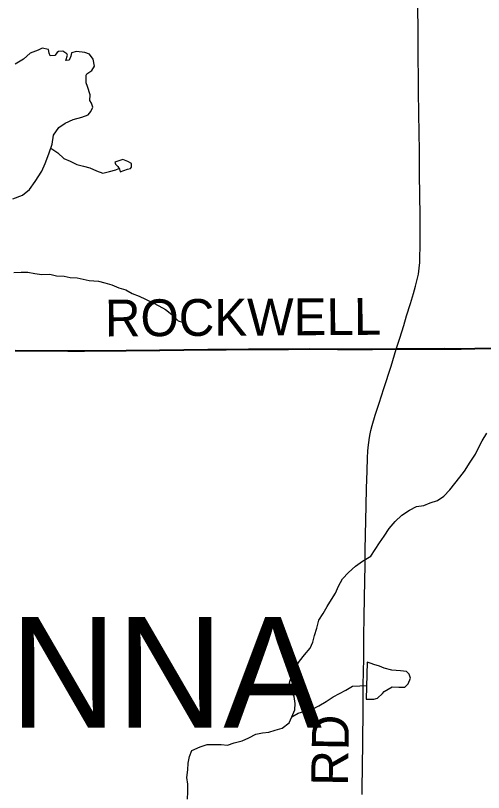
# Model space of a CAD drawing. Extents: x 0 to 34, y 0 to 22.
# Drawn here: x 23.748 to 24.47, y 12.038 to 13.237 of the extents above; entities that cross this region are included whole.
import ezdxf

# ---------------------------------------------------------------- set-up
doc = ezdxf.new("R2010")
doc.units = 0
for name, color, linetype in [('GM_X_Corporation', 7, 'Continuous'), ('GM_X_County_Road', 7, 'Continuous'), ('GM_X_County_Road_Text', 7, 'Continuous'), ('GM_X_Minor_Lake', 7, 'Continuous'), ('GM_X_Minor_River', 7, 'Continuous'), ('GM_X_Township_Text', 7, 'Continuous')]:
    doc.layers.add(name, color=color, linetype=linetype)

msp = doc.modelspace()

# ---------------------------------------------------------------- linework, layer by layer
at = {"layer": 'GM_X_Corporation'}
for points in [[(24.6023, 12.724), (24.4568, 12.7229), (24.4357, 12.7227), (24.4096, 12.7228), (24.3873, 12.7226), (24.3619, 12.7226), (24.3353, 12.7224), (24.299, 12.7222), (24.2598, 12.7221), (24.245, 12.7222), (24.2022, 12.7224), (24.1693, 12.7222), (24.1078, 12.7219), (24.0731, 12.7215), (24.0451, 12.7213), (23.9705, 12.7205), (23.919, 12.7199), (23.8904, 12.7197), (23.8543, 12.7197), (23.8289, 12.7197), (23.7792, 12.7197), (23.7663, 12.7197), (23.7477, 12.7198)], [(23.7477, 12.7198), (23.7663, 12.7197), (23.7792, 12.7197), (23.8289, 12.7197), (23.8543, 12.7197), (23.8904, 12.7197), (23.919, 12.7199), (23.9705, 12.7205), (24.0451, 12.7213), (24.0731, 12.7215), (24.1078, 12.7219), (24.1693, 12.7222), (24.2022, 12.7224), (24.245, 12.7222), (24.2598, 12.7221), (24.299, 12.7222), (24.3353, 12.7224), (24.3619, 12.7226), (24.3873, 12.7226), (24.4096, 12.7228), (24.4357, 12.7227), (24.4568, 12.7229), (24.6023, 12.724)]]:
    msp.add_lwpolyline(points, dxfattribs=at)
at = {"layer": 'GM_X_County_Road'}
for points in [[(24.3355, 12.7219), (24.3411, 12.7391), (24.3472, 12.7587), (24.3517, 12.7733), (24.3577, 12.7927), (24.3622, 12.8079), (24.3654, 12.8191), (24.367, 12.8252), (24.3685, 12.8313), (24.3698, 12.8376), (24.3705, 12.8422), (24.3711, 12.8468), (24.3715, 12.8514), (24.3718, 12.8553), (24.3722, 12.8685), (24.3724, 12.8757), (24.3724, 12.8845), (24.3724, 12.8999), (24.3723, 12.9281), (24.3715, 12.9914), (24.3713, 13.0297), (24.371, 13.0537), (24.3706, 13.0876), (24.3702, 13.1174), (24.3701, 13.1281), (24.3699, 13.1407), (24.3697, 13.1714), (24.3694, 13.2024), (24.3689, 13.2618)], [(24.3355, 12.7219), (24.3621, 12.722), (24.3875, 12.722), (24.4098, 12.7222), (24.4359, 12.7222), (24.457, 12.7223), (24.6025, 12.7234), (24.654, 12.7236), (24.6795, 12.7237), (24.8466, 12.7253), (24.9175, 12.726), (24.9759, 12.7265), (25.1339, 12.7271)], [(23.7479, 12.7192), (23.7665, 12.7192), (23.7794, 12.7192), (23.8291, 12.7191), (23.8545, 12.7191), (23.8906, 12.7192), (23.9192, 12.7193), (23.9708, 12.72), (24.0453, 12.7208), (24.0733, 12.721), (24.108, 12.7213), (24.1695, 12.7216), (24.2024, 12.7218), (24.2452, 12.7217), (24.2601, 12.7216), (24.2992, 12.7217), (24.3355, 12.7219)], [(24.2831, 12.0354), (24.2833, 12.0503), (24.2834, 12.072), (24.2841, 12.1211), (24.2845, 12.1608), (24.2847, 12.1894), (24.2848, 12.2019), (24.2853, 12.2267), (24.2855, 12.2428), (24.2855, 12.2608), (24.2856, 12.272), (24.2857, 12.28), (24.286, 12.3086), (24.2865, 12.339), (24.2875, 12.3894), (24.2879, 12.4125), (24.2894, 12.4811), (24.2899, 12.5071), (24.2907, 12.5344), (24.2914, 12.5544), (24.292, 12.5648), (24.2924, 12.5706), (24.2932, 12.5783), (24.2942, 12.586), (24.2952, 12.5916), (24.2965, 12.5968), (24.2986, 12.6045), (24.3032, 12.62), (24.3053, 12.6265), (24.3092, 12.6388), (24.3165, 12.6613), (24.3276, 12.6956), (24.3355, 12.7219)]]:
    msp.add_lwpolyline(points, dxfattribs=at)
at = {"layer": 'GM_X_Minor_Lake'}
for p, q in [((23.9096, 12.9957), (23.921, 12.9996)), ((24.2906, 12.2391), (24.2892, 12.1822))]:
    msp.add_line(p, q, dxfattribs=at)
for points in [[(23.7442, 12.9539), (23.7589, 12.9593), (23.7698, 12.9685), (23.7788, 12.9807), (23.7889, 12.9967), (23.7941, 13.0085), (23.7997, 13.0234), (23.8049, 13.0382), (23.8066, 13.0518), (23.8149, 13.0637), (23.8247, 13.0706), (23.8371, 13.0764), (23.8503, 13.0799), (23.8605, 13.0834), (23.8643, 13.0887), (23.8676, 13.0952), (23.8657, 13.1016), (23.863, 13.1054), (23.8633, 13.1141), (23.8591, 13.127), (23.8571, 13.133), (23.8574, 13.1444), (23.8585, 13.1467), (23.8661, 13.1517), (23.8702, 13.1585), (23.8682, 13.1691), (23.8624, 13.1771), (23.8552, 13.1797), (23.8424, 13.1811), (23.8344, 13.1791), (23.8337, 13.1738), (23.8311, 13.1677), (23.8258, 13.1673), (23.8284, 13.1753), (23.8272, 13.1775), (23.8212, 13.1817), (23.8147, 13.1812), (23.8125, 13.1793), (23.8091, 13.1751), (23.8015, 13.1743), (23.8, 13.1785), (23.7992, 13.1842), (23.7893, 13.186), (23.7833, 13.1833), (23.7708, 13.1786), (23.7607, 13.1691), (23.7479, 13.1618)], [(23.921, 12.9996), (23.9255, 13.0004), (23.927, 13.0027), (23.927, 13.0084), (23.9216, 13.0114), (23.914, 13.0144), (23.9016, 13.0105), (23.9027, 13.0071), (23.9062, 13.0037), (23.9085, 12.9995), (23.9096, 12.9957)], [(24.2892, 12.1822), (24.3009, 12.1823), (24.3066, 12.1838), (24.3145, 12.1911), (24.3171, 12.1942), (24.3292, 12.2011), (24.3394, 12.2008), (24.3489, 12.2008), (24.3541, 12.2058), (24.3574, 12.2146), (24.3555, 12.221), (24.3517, 12.2247), (24.3422, 12.2258), (24.329, 12.2272), (24.3168, 12.2298), (24.31, 12.2332), (24.3013, 12.2357), (24.2967, 12.2372), (24.2906, 12.2391)]]:
    msp.add_lwpolyline(points, dxfattribs=at)
at = {"layer": 'GM_X_Minor_River'}
for points in [[(23.8027, 13.0321), (23.8133, 13.025), (23.8228, 13.0159), (23.8323, 13.0122), (23.843, 13.0066), (23.8532, 13.0044), (23.8631, 13.0015), (23.8733, 12.997), (23.8832, 12.9933), (23.893, 12.996), (23.9032, 12.9987), (23.9078, 13.0008)], [(23.7458, 12.8405), (23.7568, 12.841), (23.767, 12.8407), (23.778, 12.8389), (23.7886, 12.8374), (23.8011, 12.8375), (23.8114, 12.8353), (23.8231, 12.8347), (23.8326, 12.8328), (23.8436, 12.8318), (23.8621, 12.8281), (23.8765, 12.8271), (23.886, 12.8245), (23.8966, 12.8212), (23.9076, 12.8167), (23.9186, 12.8134), (23.9281, 12.8078), (23.9391, 12.8037), (23.9597, 12.794), (23.9695, 12.7891), (23.9798, 12.7831), (23.9893, 12.7756), (23.9992, 12.7658), (24.0057, 12.7636)], [(24.2728, 12.3872), (24.2837, 12.3952), (24.2962, 12.4029), (24.3033, 12.4132), (24.31, 12.4235), (24.3171, 12.4338), (24.3246, 12.4456), (24.334, 12.4563), (24.3441, 12.4662), (24.3562, 12.4739), (24.3667, 12.4793), (24.3781, 12.4809), (24.3879, 12.4851), (24.3992, 12.4886), (24.409, 12.4952), (24.4184, 12.5051), (24.4262, 12.5146), (24.4337, 12.5246), (24.4412, 12.5341), (24.4498, 12.5478), (24.4577, 12.56), (24.4633, 12.571), (24.4681, 12.5806), (24.4752, 12.5924)], [(24.0138, 12.028), (24.014, 12.0394), (24.014, 12.0512), (24.0127, 12.0614), (24.0142, 12.0732), (24.0148, 12.0834), (24.0166, 12.0937), (24.0204, 12.1032), (24.0332, 12.1089), (24.0441, 12.1121), (24.0551, 12.1125), (24.0657, 12.1122), (24.0755, 12.1115), (24.0857, 12.1147), (24.0978, 12.1178), (24.1084, 12.1228), (24.1189, 12.1282), (24.1291, 12.1302), (24.139, 12.1314), (24.1488, 12.1345), (24.1597, 12.1376), (24.1703, 12.1456), (24.1747, 12.1551), (24.1792, 12.1658), (24.1795, 12.1757), (24.1779, 12.1863), (24.1729, 12.1961), (24.1709, 12.2074), (24.1746, 12.2196), (24.1791, 12.2299), (24.1862, 12.2409), (24.194, 12.2505), (24.203, 12.2608), (24.2068, 12.2703), (24.2097, 12.2802), (24.213, 12.2919), (24.2163, 12.3041), (24.2227, 12.3144), (24.229, 12.3251), (24.2358, 12.3361), (24.2417, 12.3456), (24.2466, 12.3567), (24.2525, 12.3677), (24.2619, 12.3776), (24.2728, 12.3872)], [(24.1747, 12.1551), (24.1845, 12.1609), (24.1944, 12.1636), (24.2053, 12.1664), (24.2162, 12.1718), (24.2275, 12.1787), (24.2381, 12.1856), (24.2479, 12.191), (24.2581, 12.196), (24.2682, 12.2021), (24.2796, 12.203), (24.2897, 12.2035)]]:
    msp.add_lwpolyline(points, dxfattribs=at)

# ---------------------------------------------------------------- texts
at = {"layer": 'GM_X_County_Road_Text'}
for s, rotation, p in [('ROCKWELL', 0.3709, (23.8863, 12.7415)), ('RD', 89.0138, (24.2611, 12.0481))]:
    msp.add_text(s, height=0.05682, rotation=rotation, dxfattribs=at).set_placement(p)
at = {"layer": 'GM_X_Township_Text'}
msp.add_text('RAVENNA', height=0.17045, rotation=0, dxfattribs=at).set_placement((23.119, 12.1384))

doc.saveas('drawing.dxf')
